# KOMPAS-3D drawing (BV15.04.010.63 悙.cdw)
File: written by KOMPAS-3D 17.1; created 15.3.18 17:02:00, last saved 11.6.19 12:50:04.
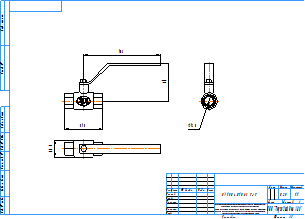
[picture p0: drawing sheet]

Sheet 1: A3, landscape

Title block, sheet 1: name: BV15.04.010.63 Р/Р; material: Внимание! Данный продукт является объектом авторского права ООО «Торговый Дом АДЛ». / Запрещается изменение, копирование, распространение / (в том числе путем копирования на другие сайты и ресурсы в Интернете) / или любое иное использование информации и объектов без предварительного / согласия правообладателя (ООО «Торговый Дом АДЛ»).; mass: 0,25; sheets: 1; organisation: ООО "Торговый дом АДЛ"; sheet format: A3; stored path: \\adlc.lan\data\АДЛ_ПКД\3D-модели\ADL production\Краны шаровые серии BV\BV15\KOMPAS 2D\BV15.04.010.63 РР.cdw

Views: Вид 1, Проекционный вид 2, Проекционный вид 3
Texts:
  kka
  adl
Dimensions and other numbers on the sheet: 51,5; 103; 51; 12,5; 22,5; 1:1; 1; 0,25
